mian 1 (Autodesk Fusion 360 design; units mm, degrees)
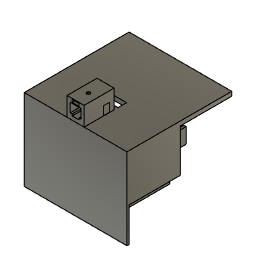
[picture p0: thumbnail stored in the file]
sketch "草图1" plane through (0, 0, 0) normal (0, 0, 1) x axis (1, 0, 0)
  line L1 (60, 60) -> (-60, 60)
  line L2 (60, -60) -> (60, 60)
  line L3 (-60, -60) -> (60, -60)
  line L4 (-60, 60) -> (-60, -60)
  line L5 (60, -60) -> (-60, 60)
  line L6 (-60, -60) -> (60, 60)
  point P6 (0, 0)
  point P1 (0, 0)
  point P4 (60, -60)
  point P5 (-60, -60)
  horizontal L1
  perpendicular L1 L2
  parallel L1 L3
  parallel L2 L4
  coincident L5 P6
  coincident L6 P6
  coincident P1 P6
  dimension "d1" distance P4 P5 = 120
  dimension "d2" distance L1 L3 = 120
sketch "草图2" plane through (0, -60, 0) normal (0, -1, 0) x axis (1, 0, 0)
  line L1 (60, 0) -> (-60, 0)
  line L2 (60, 90) -> (60, 0)
  line L3 (-60, 90) -> (60, 90)
  line L4 (-60, 0) -> (-60, 90)
  line L5 (55, 90) -> (-55, 90)
  line L6 (55, 5) -> (55, 90)
  line L7 (-55, 5) -> (55, 5)
  line L8 (-55, 90) -> (-55, 5)
  point P6 (-55, 90)
  horizontal L5
  vertical L6
  horizontal L7
  vertical L8
  coincident L3 P6
  dimension "d5" distance L4 L8 = 5
  dimension "d19" distance L1 L7 = 5
sketch "草图11" plane through (0, -60, 0) normal (0, -1, 0) x axis (1, 0, 0)
  line L1 (-55, 90) -> (-55, 5)
  line L2 (-60, 90) -> (-55, 90)
  line L3 (-60, 0) -> (-60, 90)
  line L4 (60, 0) -> (-60, 0)
  line L5 (60, 90) -> (60, 0)
  line L6 (55, 90) -> (60, 90)
  line L7 (55, 5) -> (55, 90)
  line L8 (-55, 5) -> (55, 5)
  line L9 (-58, 85) -> (-55, 85)
  line L10 (-58, 75) -> (-58, 85)
  line L11 (-55, 75) -> (-58, 75)
  line L12 (-55, 85) -> (-55, 75)
  point P10 (-55, 85)
  horizontal L9
  vertical L10
  horizontal L11
  vertical L12
  coincident L1 P10
  dimension "d45" distance L10 L12 = 3
  dimension "d46" distance L9 L11 = 10
  dimension "d47" distance L2 L9 = 5
sketch "草图12" plane through (-60, 0, 0) normal (-1, 0, 0) x axis (0, -1, 0)
  line L1 (60, 0) -> (-60, 0)
  line L2 (60, 90) -> (60, 0)
  line L3 (-60, 90) -> (60, 90)
  line L4 (-60, 0) -> (-60, 90)
  line L5 (60, 90) -> (0, 90)
  line L6 (60, 40) -> (60, 90)
  line L7 (0, 40) -> (60, 40)
  line L8 (0, 90) -> (0, 40)
  point P8 (60, 40)
  point P6 (0, 90)
  horizontal L5
  vertical L6
  horizontal L7
  vertical L8
  coincident L2 P8
  midpoint L3 P6
  dimension "d50" distance L5 L7 = 50
sketch "草图13" plane through (0, 0, 0) normal (0, -1, 0) x axis (1, 0, 0)
  line L1 (-55, 90) -> (-55, 40)
  line L2 (-60, 90) -> (-55, 90)
  line L3 (-60, 40) -> (-60, 90)
  line L4 (-55, 40) -> (-60, 40)
  line L5 (-58, 85) -> (-55, 85)
  line L6 (-58, 65) -> (-58, 85)
  line L7 (-55, 65) -> (-58, 65)
  line L8 (-55, 85) -> (-55, 65)
  point P6 (-55, 85)
  horizontal L5
  vertical L6
  horizontal L7
  vertical L8
  coincident L1 P6
  dimension "d53" distance L5 L7 = 20
  dimension "d54" distance L2 L5 = 5
  dimension "d55" distance L6 L8 = 3
mirror "镜像1" mirrorStitchTolerance 0.1
sketch "草图14" plane through (0, -60, 0) normal (0, -1, 0) x axis (1, 0, 0)
  line L1 (-60, 40) -> (-55, 40)
  line L2 (-60, 0) -> (-60, 40)
  line L3 (60, 0) -> (-60, 0)
  line L4 (60, 40) -> (60, 0)
  line L5 (55, 40) -> (60, 40)
  line L6 (55, 5) -> (55, 40)
  line L7 (-55, 5) -> (55, 5)
  line L8 (-55, 40) -> (-55, 5)
  line L9 (-58, 40) -> (-56, 40)
  line L10 (-58, 35) -> (-58, 40)
  line L11 (-56, 35) -> (-58, 35)
  line L12 (-56, 40) -> (-56, 35)
  point P10 (-56, 40)
  horizontal L9
  vertical L10
  horizontal L11
  vertical L12
  coincident L1 P10
  dimension "d60" distance L9 L11 = 5
  dimension "d61" distance L10 L12 = 2
  dimension "d62" distance L2 L10 = 2
mirror "镜像2" mirrorStitchTolerance 0.1
sketch "草图1" plane through (0, -60, 0) normal (0, -1, 0) x axis (1, 0, 0)
  line L1 (58, 35) -> (58, 40)
  line L2 (56, 35) -> (58, 35)
  line L3 (56, 40) -> (56, 35)
  line L4 (55, 40) -> (56, 40)
  line L5 (55, 5) -> (55, 40)
  line L6 (-55, 5) -> (55, 5)
  line L7 (-55, 40) -> (-55, 5)
  line L8 (-56, 40) -> (-55, 40)
  line L9 (-56, 35) -> (-56, 40)
  line L10 (-58, 35) -> (-56, 35)
  line L11 (-58, 40) -> (-58, 35)
  line L12 (-60, 40) -> (-58, 40)
  line L13 (-60, 0) -> (-60, 40)
  line L14 (60, 0) -> (-60, 0)
  line L15 (60, 40) -> (60, 0)
  line L16 (58, 40) -> (60, 40)
  line L17 (-57.9, 35) -> (-56.1, 35)
  line L18 (-57.9, 39.9) -> (-57.9, 35)
  line L19 (-56.1, 39.9) -> (-57.9, 39.9)
  line L20 (-56.1, 35) -> (-56.1, 39.9)
  line L21 (57.9, 40) -> (56.1, 40)
  line L22 (57.9, 35.1) -> (57.9, 40)
  line L23 (56.1, 35.1) -> (57.9, 35.1)
  line L24 (56.1, 40) -> (56.1, 35.1)
  point P18 (-56.1, 35)
  horizontal L17
  vertical L18
  horizontal L19
  vertical L20
  coincident L10 P18
  horizontal L21
  vertical L22
  horizontal L23
  vertical L24
  dimension "d82" distance L17 L19 = 4.9
  dimension "d83" distance L18 L20 = 1.8
  dimension "d84" distance L9 L20 = 0.1
  dimension "d85" distance L22 L24 = 1.8
  dimension "d86" distance L21 L23 = 4.9
  dimension "d87" distance L1 L22 = 0.1
mirror_component "镜像零部件"
derived_instance "DerivedInstance1"
remove_instance "移除实例"
extrude "拉伸6" new body of existing geometry blind 50
sketch "草图2" plane through (0, -60, 0) normal (0, -1, 0) x axis (1, 0, 0)
  line L1 (58, 35) -> (58, 40)
  line L2 (56, 35) -> (58, 35)
  line L3 (56, 40) -> (56, 35)
  line L4 (55, 40) -> (56, 40)
  line L5 (55, 5) -> (55, 40)
  line L6 (-55, 5) -> (55, 5)
  line L7 (-55, 40) -> (-55, 5)
  line L8 (-56, 40) -> (-55, 40)
  line L9 (-56, 35) -> (-56, 40)
  line L10 (-58, 35) -> (-56, 35)
  line L11 (-58, 40) -> (-58, 35)
  line L12 (-60, 40) -> (-58, 40)
  line L13 (-60, 0) -> (-60, 40)
  line L14 (60, 0) -> (-60, 0)
  line L15 (60, 40) -> (60, 0)
  line L16 (58, 40) -> (60, 40)
  line L17 (-60, 95) -> (60, 95)
  line L18 (-60, 0) -> (-60, 95)
  line L19 (60, 0) -> (-60, 0)
  line L20 (60, 95) -> (60, 0)
  point P15 (-60, 0)
  point P20 (-60, 0)
  horizontal L17
  vertical L18
  horizontal L19
  vertical L20
  coincident P15 P20
  dimension "d73" distance L17 L19 = 95
extrude "拉伸2" add sketch "草图2" along normal blind 2.5
sketch "草图3" plane through (0, -60, 0) normal (0, 1, 0) x axis (-1, 0, 0)
  line L1 (-60, 0) -> (-60, 95)
  line L2 (60, 95) -> (60, 0)
  line L3 (-60, 95) -> (60, 95)
  line L4 (60, 95) -> (-60, 95)
  line L5 (60, 90) -> (60, 95)
  line L6 (-60, 90) -> (60, 90)
  line L7 (-60, 95) -> (-60, 90)
  line L8 (60, 0) -> (-60, 0)
  line L9 (-56, 40) -> (-58, 40)
  line L10 (-56, 35) -> (-56, 40)
  line L11 (-58, 35) -> (-56, 35)
  line L12 (-58, 40) -> (-58, 35)
  point P8 (60, 90)
  point P2 (-60, 95)
  point P6 (-60, 95)
  horizontal L4
  vertical L5
  horizontal L6
  vertical L7
  coincident L2 P8
  coincident P2 P6
extrude "拉伸3" add sketch "草图3" profile of L1 L2 L3 L4 L5 L6 L7 along normal blind 120
sketch "草图4" plane through (60, 0, 0) normal (1, 0, 0) x axis (0, 1, 0)
  line L1 (-60, 90) -> (-60, 0)
  line L2 (60, 90) -> (-60, 90)
  line L3 (60, 95) -> (60, 90)
  line L4 (-62.5, 95) -> (60, 95)
  line L5 (-62.5, 0) -> (-62.5, 95)
  line L6 (-60, 0) -> (-62.5, 0)
  line L7 (-60, 90) -> (0, 90)
  line L8 (-60, 40) -> (-60, 90)
  line L9 (0, 40) -> (-60, 40)
  line L10 (0, 90) -> (0, 40)
  point P10 (-60, 40)
  point P8 (0, 90)
  horizontal L7
  vertical L8
  horizontal L9
  vertical L10
  coincident L1 P10
  midpoint L2 P8
extrude "拉伸4" add sketch "草图4" profile of L1 L2 L7 L8 L9 L10 against normal blind 5
sketch "草图5" plane through (0, 0, 0) normal (0, 1, 0) x axis (-1, 0, 0)
  line L1 (-60, 40) -> (-60, 90)
  line L2 (-55, 40) -> (-60, 40)
  line L3 (-55, 90) -> (-55, 40)
  line L4 (-60, 90) -> (-55, 90)
  line L5 (-55, 65.1) -> (-58, 65.1)
  line L6 (-55, 84.9) -> (-55, 65.1)
  line L7 (-58, 84.9) -> (-55, 84.9)
  line L8 (-58, 65.1) -> (-58, 84.9)
  point P8 (-55, 84.9)
  horizontal L5
  vertical L6
  horizontal L7
  vertical L8
  coincident L3 P8
  dimension "d80" distance L4 L7 = 5.1
  dimension "d81" distance L5 L7 = 19.8
extrude "拉伸5" add sketch "草图5" profile of L3 L5 L6 L7 L8 along normal blind 9.8
mirror "镜像2" mirrorStitchTolerance 0.1
mirror "镜像3" mirrorStitchTolerance 0.1
mirror "镜像4" mirrorStitchTolerance 0.1
sketch "草图2" plane through (0, 0, 95) normal (0, 0, 1) x axis (-1, 0, 0)
  line L1 (60, 62.5) -> (60, -60)
  line L2 (-60, 62.5) -> (60, 62.5)
  line L3 (-60, -60) -> (-60, 62.5)
  line L4 (60, -60) -> (-60, -60)
  line L5 (-10, 50) -> (10, 50)
  line L6 (-10, 15) -> (-10, 50)
  line L7 (10, 15) -> (-10, 15)
  line L8 (10, 50) -> (10, 15)
  horizontal L5
  vertical L6
  horizontal L7
  vertical L8
  dimension "d96" distance L6 L8 = 20
  dimension "d97" distance L5 L7 = 35
extrude "拉伸1" new body sketch "草图2" profile of L5 L6 L7 L8 along normal blind 20
sketch "草图3" plane through (0, -15, 0) normal (0, 1, 0) x axis (-1, 0, 0)
  line L1 (10, 95) -> (-10, 95)
  line L2 (10, 115) -> (10, 95)
  line L3 (-10, 115) -> (10, 115)
  line L4 (-10, 95) -> (-10, 115)
  line L5 (-6.2, 111.8736) -> (-6.2, 112)
  line L6 (-6, 101.3) -> (-6.2, 101.3)
  line L7 (6.5, 101.3) -> (6.35, 101.3)
  line L8 (6.35, 112) -> (-6.35, 112)
  line L9 (6.35, 101.3) -> (6.35, 112)
  line L10 (-6.35, 112) -> (-6.35, 101.3)
  line L11 (5.4209, 102.0827) -> (-6.35, 112)
  line L12 (-6.35, 101.3) -> (6.35, 112)
  line L13 (3.9991, 99.3) -> (3.9991, 101.3)
  line L14 (-4.0009, 99.3) -> (3.9991, 99.3)
  line L15 (-4.0009, 101.3) -> (-4.0009, 99.3)
  line L16 (3.9991, 99.3) -> (-4.0009, 101.3)
  line L17 (-4.0009, 99.3) -> (3.9991, 101.3)
  line L18 (3.9991, 101.3) -> (6.35, 101.3)
  line L19 (-6.35, 101.3) -> (-4.0009, 101.3)
  line L20 (3.9991, 99.3) -> (3.9991, 101.3)
  line L21 (-4.0009, 101.3) -> (-4.0009, 99.3)
  line L22 (3.9991, 99.3) -> (3.9991, 101.3)
  point P13 (0, 106.65)
  point P14 (-6.2, 112)
  point P15 (-6.2, 111.8736)
  point P17 (6.35, 101.3)
  point P22 (-0.0009, 100.3)
  point P18 (-4.0009, 101.3)
  point P21 (-4.0009, 99.3)
  vertical L5
  horizontal L6
  collinear L6 L7
  horizontal L8
  perpendicular L8 L9
  parallel L8 L18
  parallel L9 L10
  coincident L11 P13
  coincident L12 P13
  coincident L8 P14
  coincident L11 P15
  coincident L9 P17
  parallel L13 L15
  coincident L16 P22
  coincident L17 P22
  coincident P18 L18
  collinear L18 L19
  perpendicular L14 L20
  perpendicular L19 L21
  dimension "d176" distance L8 L18 = 10.7
  dimension "d177" distance L9 L10 = 12.7
  dimension "d178" distance L3 L8 = 3
  dimension "d179" distance L2 L9 = 3.65
  dimension "d180" distance P18 P21 = 2
  dimension "d181" distance L13 L15 = 8
sketch "草图4" plane through (0, 0, 95) normal (0, 0, -1) x axis (1, 0, 0)
  line L1 (-10, 15) -> (-10, 50)
  line L2 (10, 15) -> (-10, 15)
  line L3 (10, 50) -> (10, 15)
  line L4 (-10, 50) -> (10, 50)
  line L5 (-7.391, 41) -> (7.609, 41)
  line L6 (-7.391, 36) -> (-7.391, 41)
  line L7 (7.609, 36) -> (-7.391, 36)
  line L8 (7.609, 41) -> (7.609, 36)
  horizontal L5
  vertical L6
  horizontal L7
  vertical L8
  dimension "d107" distance L5 L7 = 5
  dimension "d108" distance L6 L8 = 15
sketch "草图5" plane through (0, 0, 0) normal (0, 0, -1) x axis (1, 0, 0)
  line L1 (-60, 60) -> (60, 60)
  line L2 (-60, -60) -> (-60, 60)
  line L3 (60, -60) -> (-60, -60)
  line L4 (60, 60) -> (60, -60)
  line L5 (-32, -40) -> (-45, -40)
  line L6 (-32, -52) -> (-32, -40)
  line L7 (-45, -52) -> (-32, -52)
  line L8 (-45, -40) -> (-45, -52)
  horizontal L5
  vertical L6
  horizontal L7
  vertical L8
  dimension "d113" distance L5 L7 = 12
  dimension "d114" distance L6 L8 = 13
  dimension "d115" distance L2 L8 = 15
sketch "草图6" plane through (0, 0, 90) normal (0, 0, -1) x axis (1, 0, 0)
  line L1 (-60, 0) -> (-55, 0)
  line L2 (-60, -60) -> (-60, 0)
  line L3 (60, -60) -> (-60, -60)
  line L4 (60, 0) -> (60, -60)
  line L5 (55, 0) -> (60, 0)
  line L6 (55, 60) -> (55, 0)
  line L7 (-55, 60) -> (55, 60)
  line L8 (-55, 0) -> (-55, 60)
  line L9 (-7.4, 36) -> (7.6, 36)
  line L10 (-7.4, 46) -> (-7.4, 36)
  line L11 (7.6, 46) -> (-7.4, 46)
  line L12 (7.6, 36) -> (7.6, 46)
  horizontal L9
  vertical L10
  horizontal L11
  vertical L12
  dimension "d161" distance L9 L11 = 10
position "位置"
extrude "拉伸9" cut of existing geometry blind -1
extrude "拉伸10" cut of existing geometry blind -1
extrude "拉伸11" cut of existing geometry blind -1
extrude "拉伸12" cut of existing geometry blind -1
extrude "拉伸13" cut of existing geometry blind -1
extrude "拉伸14" cut of existing geometry blind -1
extrude "拉伸15" cut of existing geometry blind -0.5
extrude "拉伸16" cut of existing geometry blind -0.5
extrude "拉伸17" cut of existing geometry blind -0.5
extrude "拉伸18" cut of existing geometry blind -0.5
extrude "拉伸15" add of existing geometry blind 2
sketch "草图15" plane through (0, -62.5, 0) normal (0, -1, 0) x axis (1, 0, 0)
  line L1 (10, 95) -> (-10, 95)
  line L2 (10, 117) -> (10, 95)
  line L3 (-10, 117) -> (10, 117)
  line L4 (-10, 95) -> (-10, 117)
  line L5 (-4, 113) -> (4, 113)
  line L6 (-4, 116) -> (-4, 113)
  line L7 (4, 116) -> (-4, 116)
  line L8 (4, 113) -> (4, 116)
  line L9 (-4, 116) -> (4, 113)
  line L10 (4, 116) -> (-4, 113)
  point P10 (0, 114.5)
  point P8 (-4, 116)
  point P9 (4, 116)
  horizontal L5
  perpendicular L5 L6
  parallel L5 L7
  parallel L6 L8
  coincident L9 P10
  coincident L10 P10
  dimension "d151" distance P8 P9 = 8
  dimension "d152" distance L5 L7 = 3
extrude "拉伸7" cut sketch "草图15" profile of L5 L6 L7 L8 against normal blind 50
sketch "草图16" plane through (0, 0, 117) normal (0, 0, 1) x axis (-1, 0, 0)
  line L1 (10, 62.5) -> (10, 27.5)
  line L2 (-10, 62.5) -> (10, 62.5)
  line L3 (-10, 27.5) -> (-10, 62.5)
  line L4 (10, 27.5) -> (-10, 27.5)
  circle C1 centre (0, 47.5) radius 2
  point P6 (0, 47.5)
  dimension "d155" diameter C1 = 4
  dimension "d156" distance L2 P6 = 15
extrude "拉伸8" cut sketch "草图16" profile of C1 against normal blind 7
extrude "拉伸9" add of existing geometry blind 1
extrude "拉伸10" add of existing geometry blind 1
sketch "草图18" plane through (0, 0, 90) normal (0, 0, -1) x axis (1, 0, 0)
  line L1 (-60, 0) -> (-55, 0)
  line L2 (-60, -60) -> (-60, 0)
  line L3 (60, -60) -> (-60, -60)
  line L4 (60, 0) -> (60, -60)
  line L5 (55, 0) -> (60, 0)
  line L6 (55, 60) -> (55, 0)
  line L7 (-55, 60) -> (55, 60)
  line L8 (-55, 0) -> (-55, 60)
  line L9 (7.6149, 46) -> (-7.4, 46)
  line L10 (7.6149, 39) -> (7.6149, 46)
  line L11 (-7.4, 39) -> (7.6149, 39)
  line L12 (-7.4, 46) -> (-7.4, 39)
  horizontal L9
  vertical L10
  horizontal L11
  vertical L12
  dimension "d184" distance L9 L11 = 7
sketch "草图19" plane through (0, 0, 95) normal (0, 0, 1) x axis (-1, 0, 0)
  line L1 (60, 62.5) -> (60, -60)
  line L2 (-60, 62.5) -> (60, 62.5)
  line L3 (-60, -60) -> (-60, 62.5)
  line L4 (60, -60) -> (-60, -60)
  line L5 (-10, 13) -> (10, 13)
  line L6 (-10, 23) -> (-10, 13)
  line L7 (10, 23) -> (-10, 23)
  line L8 (10, 13) -> (10, 23)
  line L9 (-10, 23) -> (10, 13)
  line L10 (10, 23) -> (-10, 13)
  point P10 (0, 18)
  horizontal L5
  perpendicular L5 L6
  parallel L5 L7
  parallel L6 L8
  coincident L9 P10
  coincident L10 P10
extrude "拉伸21" cut sketch "草图19" profile of L5 L6 L7 L8 against normal blind 30
extrude "拉伸12" cut sketch "草图3" profile of L7 L8 L9 L19 L10 L13 L14 L15 L20 L21 L22 against normal blind 55
sketch "草图20" plane through (0, 0, 90) normal (0, 0, -1) x axis (1, 0, 0)
  line L1 (10, 13) -> (10, 23)
  line L2 (-10, 13) -> (10, 13)
  line L3 (-10, 23) -> (-10, 13)
  line L4 (10, 23) -> (-10, 23)
  line L5 (-60, 0) -> (-55, 0)
  line L6 (-60, -60) -> (-60, 0)
  line L7 (60, -60) -> (-60, -60)
  line L8 (60, 0) -> (60, -60)
  line L9 (55, 0) -> (60, 0)
  line L10 (55, 60) -> (55, 0)
  line L11 (-55, 60) -> (55, 60)
  line L12 (-55, 0) -> (-55, 60)
  line L13 (9.625, 39.5) -> (-9.625, 39.5)
  line L14 (9.625, 32.5) -> (9.625, 39.5)
  line L15 (-9.625, 32.5) -> (9.625, 32.5)
  line L16 (-9.625, 39.5) -> (-9.625, 32.5)
  line L17 (9.625, 32.5) -> (-9.625, 39.5)
  line L18 (-9.625, 32.5) -> (9.625, 39.5)
  line L19 (60, 62.5) -> (-60, 62.5)
  point P18 (0, 36)
  horizontal L13
  perpendicular L13 L14
  parallel L13 L15
  parallel L14 L16
  coincident L17 P18
  coincident L18 P18
  dimension "d185" distance L13 L15 = 7
  dimension "d186" distance L13 L19 = 23
extrude "拉伸22" cut sketch "草图20" profile of L13 L14 L15 L16 against normal blind 15
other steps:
extrude "拉伸5" add of existing geometry blind 2
extrude "拉伸13" cut sketch "草图20" profile of L13 L14 L15 L16 against normal blind 15
derived_base_feature "Derived Base Feature"
create_component "创建零部件1"
create_component "创建零部件2"
create_component "创建零部件3"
